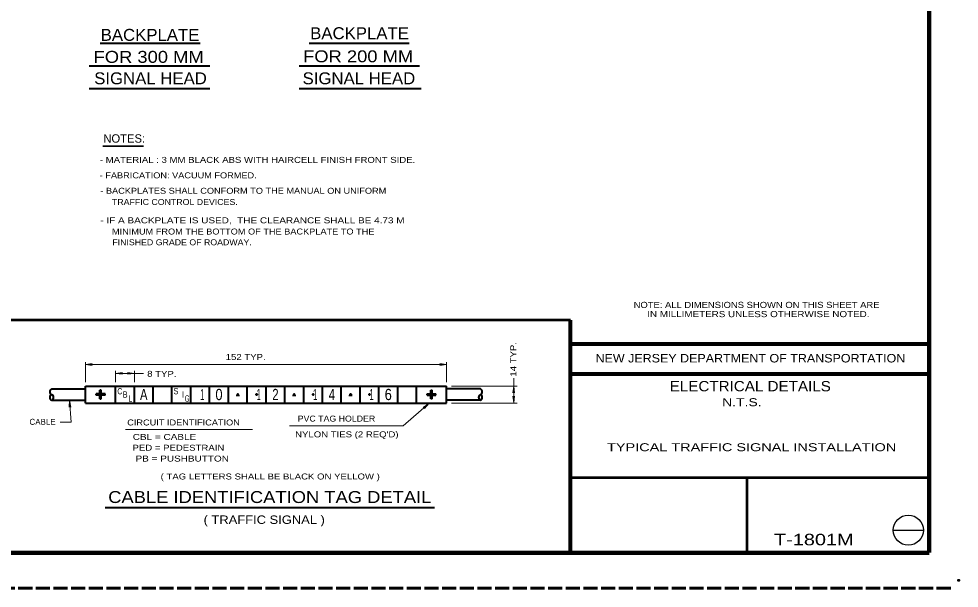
# Model space of a CAD drawing. Extents: x 312583 to 312853, y 144419 to 144586.
# Drawn here: x 312733 to 312852.8, y 144418.6 to 144491.1 of the extents above; entities that cross this region are included whole.
import ezdxf
from ezdxf.enums import TextEntityAlignment as Align

# ---------------------------------------------------------------- set-up
doc = ezdxf.new("R2010")
doc.units = 0
doc.header["$LTSCALE"] = 0.3
doc.header["$PDMODE"] = 32
doc.header["$PDSIZE"] = 0.15
doc.linetypes.add('LONG_DASHED', pattern=[7.5, 6, -1.5])
for name, color, linetype, lineweight in [('1', 7, 'Continuous', 40), ('10', 7, 'Continuous', 25), ('2', 7, 'Continuous', 13), ('63', 7, 'LONG_DASHED', 60)]:
    doc.layers.add(name, color=color, linetype=linetype, lineweight=lineweight)
doc.layers.add('5', color=7, linetype='Continuous')

msp = doc.modelspace()

# ---------------------------------------------------------------- linework, layer by layer
at = {"layer": '1', "lineweight": 158}
for p, q in [((312849, 144423.1446), (312849, 144585.0846)), ((312616.5, 144423.0846), (312849, 144423.0846))]:
    msp.add_line(p, q, dxfattribs=at)
at = {"layer": '1', "lineweight": 106}
msp.add_line((312849, 144423.1446), (312849, 144584.0756), dxfattribs=at)
at = {"layer": '1', "lineweight": 53}
for p, q in [((312803.31, 144452.7259), (312668.2732, 144452.7259)), ((312849, 144432.6666), (312803.31, 144432.6666)), ((312825.7546, 144432.6666), (312825.7546, 144423.1446))]:
    msp.add_line(p, q, dxfattribs=at)
at = {"layer": '1', "lineweight": 80}
for p, q in [((312803.31, 144423.1446), (312803.31, 144452.7259)), ((312803.31, 144449.7246), (312849, 144449.7246)), ((312803.31, 144445.9146), (312849, 144445.9146))]:
    msp.add_line(p, q, dxfattribs=at)
at = {"layer": '1'}
for p, q in [((312741.5243, 144442.1851), (312741.5243, 144444.3471)), ((312741.5243, 144444.3471), (312787.5243, 144444.3471)), ((312745.3576, 144442.1851), (312745.3576, 144444.3471)), ((312747.7496, 144442.1851), (312747.7496, 144444.3471)), ((312750.1493, 144442.1851), (312750.1493, 144444.3471)), ((312752.5413, 144442.1851), (312752.5413, 144444.3471)), ((312754.9409, 144442.1851), (312754.9409, 144444.3471)), ((312757.3329, 144442.1851), (312757.3329, 144444.3471)), ((312759.7326, 144442.1851), (312759.7326, 144444.3471)), ((312762.1246, 144442.1851), (312762.1246, 144444.3471)), ((312764.5243, 144442.1851), (312764.5243, 144444.3471)), ((312766.9239, 144442.1851), (312766.9239, 144444.3471)), ((312769.3159, 144442.1851), (312769.3159, 144444.3471)), ((312771.7156, 144442.1851), (312771.7156, 144444.3471)), ((312774.1076, 144442.1851), (312774.1076, 144444.3471)), ((312776.5073, 144442.1851), (312776.5073, 144444.3471)), ((312778.8993, 144442.1851), (312778.8993, 144444.3471)), ((312781.2989, 144442.1851), (312781.2989, 144444.3471)), ((312783.6909, 144442.1851), (312783.6909, 144444.3471)), ((312787.5243, 144442.1851), (312787.5243, 144444.3471)), ((312737.2156, 144443.9791), (312741.5243, 144443.9791)), ((312791.8329, 144443.9791), (312787.5243, 144443.9791)), ((312737.2156, 144442.5454), (312741.5243, 144442.5454)), ((312741.5243, 144442.1851), (312787.5243, 144442.1851)), ((312791.8329, 144442.5454), (312787.5243, 144442.5454)), ((312744.0476, 144428.8756), (312786.0013, 144428.8756))]:
    msp.add_line(p, q, dxfattribs=at)
at = {"layer": '1', "lineweight": 13}
msp.add_line((312739.6919, 144439.7317), (312738.2966, 144439.7317), dxfattribs=at)
at = {"layer": '1'}
for centre, start, end in [((312737.3699, 144443.6264), 113.18435, 246.81565), ((312737.3699, 144442.9057), 113.18435, 246.81565), ((312737.0613, 144442.9057), 293.18435, 66.81565), ((312791.9873, 144442.9057), 113.18435, 246.81565), ((312791.6786, 144443.6264), 293.18435, 66.81565), ((312791.6786, 144442.9057), 293.18435, 66.81565)]:
    msp.add_arc(centre, 0.392, start, end, dxfattribs=at)
for p in [(312743.4409, 144443.2661), (312760.9363, 144443.2661), (312763.3283, 144443.2661), (312768.1123, 144443.2661), (312770.5196, 144443.2661), (312775.2959, 144443.2661), (312777.7033, 144443.2661), (312785.6076, 144443.2661), (312852.75, 144419.5846)]:
    msp.add_point(p, dxfattribs=at)
at = {"layer": '10'}
msp.add_line((312844.4384, 144425.9659), (312848.2794, 144425.9659), dxfattribs=at)
msp.add_circle((312846.3494, 144425.9805), 1.9159, dxfattribs=at)
at = {"layer": '2', "lineweight": 40}
for p, q in [((312743.3954, 144488.0353), (312756.145, 144488.0353)), ((312770.0329, 144488.0353), (312782.7635, 144488.0353)), ((312741.9696, 144485.1603), (312757.3478, 144485.1603)), ((312768.7573, 144485.1603), (312784.0647, 144485.1603)), ((312741.9696, 144482.2853), (312757.3478, 144482.2853)), ((312768.7573, 144482.2853), (312784.2815, 144482.2853)), ((312742.8813, 144443.1741), (312742.8813, 144443.3504)), ((312743.3566, 144443.3504), (312742.8813, 144443.3504)), ((312743.3566, 144443.1741), (312742.8813, 144443.1741)), ((312743.5329, 144443.8334), (312743.3566, 144443.8334)), ((312743.3566, 144443.3504), (312743.3566, 144443.8334)), ((312743.3566, 144442.6987), (312743.3566, 144443.1741)), ((312743.5329, 144443.3504), (312743.5329, 144443.8334)), ((312744.0083, 144443.3504), (312743.5329, 144443.3504)), ((312743.5329, 144442.6987), (312743.5329, 144443.1741)), ((312744.0083, 144443.1741), (312743.5329, 144443.1741)), ((312744.0083, 144443.1741), (312744.0083, 144443.3504)), ((312785.0403, 144443.1741), (312785.0403, 144443.3504)), ((312785.0403, 144443.3504), (312785.5156, 144443.3504)), ((312785.0403, 144443.1741), (312785.5156, 144443.1741)), ((312785.5156, 144443.8334), (312785.6919, 144443.8334)), ((312785.5156, 144443.3504), (312785.5156, 144443.8334)), ((312785.5156, 144442.6987), (312785.5156, 144443.1741)), ((312785.6919, 144443.3504), (312785.6919, 144443.8334)), ((312785.6919, 144443.3504), (312786.1673, 144443.3504)), ((312785.6919, 144442.6987), (312785.6919, 144443.1741)), ((312785.6919, 144443.1741), (312786.1673, 144443.1741)), ((312786.1673, 144443.1741), (312786.1673, 144443.3504)), ((312743.3566, 144442.6987), (312743.5329, 144442.6987)), ((312785.6919, 144442.6987), (312785.5156, 144442.6987))]:
    msp.add_line(p, q, dxfattribs=at)
at = {"layer": '2', "lineweight": 35}
msp.add_line((312743.7271, 144474.9214), (312748.9321, 144474.9214), dxfattribs=at)
at = {"layer": '2'}
for p, q in [((312741.5243, 144444.8454), (312741.5243, 144447.3984)), ((312741.5243, 144447.0917), (312742.3906, 144447.1991)), ((312741.5243, 144447.0917), (312742.3906, 144446.9844)), ((312742.3906, 144447.1991), (312742.1146, 144447.0917)), ((312742.3906, 144446.9844), (312742.1146, 144447.0917)), ((312786.6579, 144447.1991), (312786.9339, 144447.0917)), ((312787.5243, 144447.0917), (312786.6579, 144447.1991)), ((312786.6579, 144446.9844), (312786.9339, 144447.0917)), ((312787.5243, 144447.0917), (312786.6579, 144446.9844)), ((312787.5243, 144444.8454), (312787.5243, 144447.3984)), ((312745.3576, 144444.8454), (312745.3576, 144446.2791)), ((312745.3576, 144445.9571), (312746.2239, 144446.0644)), ((312747.7496, 144445.9571), (312745.3576, 144445.9571)), ((312745.3576, 144445.9571), (312746.2239, 144445.8497)), ((312746.2239, 144446.0644), (312745.9479, 144445.9571)), ((312746.2239, 144445.8497), (312745.9479, 144445.9571)), ((312746.8833, 144446.0644), (312747.1593, 144445.9571)), ((312747.7496, 144445.9571), (312746.8833, 144446.0644)), ((312746.8833, 144445.8497), (312747.1593, 144445.9571)), ((312747.7496, 144445.9571), (312746.8833, 144445.8497)), ((312747.7496, 144444.8454), (312747.7496, 144446.2791)), ((312748.8919, 144445.9571), (312747.7496, 144445.9571)), ((312796.5019, 144444.3471), (312788.1376, 144444.3471)), ((312796.0879, 144444.3471), (312795.9806, 144443.4807)), ((312796.0879, 144442.1927), (312796.0879, 144445.3555)), ((312796.0879, 144444.3471), (312796.1953, 144443.4807)), ((312795.9806, 144443.4807), (312796.0879, 144443.7567)), ((312795.9806, 144443.0591), (312796.0879, 144442.7831)), ((312796.0879, 144442.1927), (312795.9806, 144443.0591)), ((312796.1953, 144443.4807), (312796.0879, 144443.7567)), ((312796.1953, 144443.0591), (312796.0879, 144442.7831)), ((312796.0879, 144442.1927), (312796.1953, 144443.0591)), ((312739.4849, 144442.5301), (312739.4543, 144441.6637)), ((312739.4543, 144441.6637), (312739.5463, 144441.9474)), ((312739.6919, 144439.7317), (312739.4849, 144442.5301)), ((312739.4849, 144442.5301), (312739.6536, 144441.6714)), ((312739.6536, 144441.6714), (312739.5463, 144441.9474)), ((312785.2779, 144442.1161), (312782.0043, 144439.2717)), ((312785.2779, 144442.1161), (312784.5573, 144441.6254)), ((312785.2779, 144442.1161), (312784.6953, 144441.4644)), ((312796.5019, 144442.1851), (312788.1376, 144442.1851)), ((312784.5573, 144441.6254), (312784.8333, 144441.7251)), ((312784.6953, 144441.4644), (312784.8333, 144441.7251)), ((312746.6149, 144438.7887), (312762.7993, 144438.7887)), ((312782.0043, 144439.2717), (312767.4915, 144439.2717))]:
    msp.add_line(p, q, dxfattribs=at)
at = {"layer": '2', "lineweight": 25}
for p, q in [((312741.5243, 144444.3471), (312741.5473, 144444.3471)), ((312787.5243, 144444.3471), (312787.5013, 144444.3471))]:
    msp.add_line(p, q, dxfattribs=at)
at = {"layer": '2'}
msp.add_lwpolyline([(312787.5243, 144447.0917), (312758.4009, 144447.0917), (312741.5243, 144447.0917)], dxfattribs=at)
for p in [(312743.4409, 144443.2661), (312785.6076, 144443.2661)]:
    msp.add_point(p, dxfattribs=at)
at = {"layer": '63'}
msp.add_line((312851.75, 144418.5846), (312583.526, 144418.5846), dxfattribs=at)

# ---------------------------------------------------------------- texts
at = {"layer": '1'}
for s, width, p in [('NOTE: ALL DIMENSIONS SHOWN ON THIS SHEET ARE', 1.15, (312811.3493, 144454.2975)), ('     IN MILLIMETERS UNLESS OTHERWISE NOTED.', 1.2, (312811.3492, 144453.1275))]:
    msp.add_text(s, height=0.78, dxfattribs=dict(at, width=width)).set_placement(p)
for s, height, width, p in [('NEW JERSEY DEPARTMENT OF TRANSPORTATION', 1.08, 1.1, (312826.2285, 144447.3546)), ('ELECTRICAL DETAILS', 1.315, 1.1, (312826.2107, 144443.6759)), ('C', 0.8064, 0.65, (312745.8981, 144443.2891)), ('B', 0.805, 0.7, (312746.5727, 144442.8674)), ('L', 0.805, 0.75, (312747.232, 144442.3537)), ('A', 1.434, 0.75, (312748.9456, 144442.5531)), ('S', 0.8064, 0.7, (312753.0472, 144443.2967)), ('I', 0.805, 0.85, (312753.9481, 144442.8597)), ('G', 0.805, 0.6, (312754.4694, 144442.3537)), ('1', 1.434, 0.5, (312756.4014, 144442.5531)), ('0', 1.434, 0.85, (312758.529, 144442.5531)), ('1', 1.434, 0.5, (312763.5928, 144442.5531)), ('2', 1.434, 0.75, (312765.7202, 144442.5531)), ('1', 1.434, 0.5, (312770.7841, 144442.5531)), ('4', 1.434, 0.75, (312772.9116, 144442.5531)), ('1', 1.434, 0.5, (312777.9678, 144442.5531)), ('6', 1.434, 0.85, (312780.0953, 144442.5531))]:
    msp.add_text(s, height=height, dxfattribs=dict(at, width=width)).set_placement(p, align=Align.CENTER)
for p in [(312760.9401, 144442.5531), (312768.1161, 144442.5531), (312775.2997, 144442.5531)]:
    msp.add_text('-', height=1.434, dxfattribs=at).set_placement(p, align=Align.CENTER)
at = {"layer": '2'}
for s, height, width, p in [('BACKPLATE', 1.52, 1.05, (312749.7446, 144488.3402)), ('BACKPLATE', 1.52, 1.05, (312776.434, 144488.553)), ('FOR 300 MM', 1.52, 1.15, (312749.5658, 144485.536)), ('FOR 200 MM', 1.52, 1.15, (312776.2553, 144485.6069)), ('SIGNAL HEAD', 1.52, 1.05, (312749.8059, 144482.803)), ('SIGNAL HEAD', 1.52, 1.05, (312776.3537, 144482.8029)), ('    N.T.S.  ', 1.02, 1.3, (312824.6461, 144441.778)), ('     TYPICAL TRAFFIC SIGNAL INSTALLATION     ', 1.02, 1.35, (312826.3871, 144436.0399)), ('CABLE IDENTIFICATION TAG DETAIL', 1.52, 1.15, (312765.0009, 144429.4413)), ('( TRAFFIC SIGNAL )', 1.07, 1.15, (312764.29, 144426.7803))]:
    msp.add_text(s, height=height, dxfattribs=dict(at, width=width)).set_placement(p, align=Align.CENTER)
msp.add_text('NOTES:', height=1.07, dxfattribs=at).set_placement((312746.4568, 144475.3629), align=Align.CENTER)
for s, width, p in [('- MATERIAL : 3 MM BLACK ABS WITH HAIRCELL FINISH FRONT SIDE.', 1.2, (312743.3518, 144472.791)), ('- FABRICATION: VACUUM FORMED.', 1.15, (312743.3349, 144470.8168)), ('- BACKPLATES SHALL CONFORM TO THE MANUAL ON UNIFORM', 1.15, (312743.4147, 144468.8504)), ('TRAFFIC CONTROL DEVICES.', 1.1, (312744.8943, 144467.4244)), ('- IF A BACKPLATE IS USED,  THE CLEARANCE SHALL BE 4.73 M', 1.25, (312743.4147, 144465.086)), ('MINIMUM FROM THE BOTTOM OF THE BACKPLATE TO THE', 1.15, (312744.8943, 144463.66)), ('FINISHED GRADE OF ROADWAY.', 1.1, (312744.9403, 144462.2877)), ('152 TYP.', 1.2, (312759.3846, 144447.6697)), ('8 TYP.', 1.2, (312749.3844, 144445.521)), ('PVC TAG HOLDER', 1.1, (312768.5572, 144439.8208)), ('CIRCUIT IDENTIFICATION', 1.15, (312746.8373, 144439.3244)), ('  CBL = CABLE', 1.25, (312746.8373, 144437.4844)), ("NYLON TIES (2 REQ'D)", 1.2, (312768.2272, 144437.8103)), ('  PED = PEDESTRAIN', 1.2, (312746.8373, 144436.1044)), ('   PB = PUSHBUTTON', 1.25, (312746.8373, 144434.7244)), ('( TAG LETTERS SHALL BE BLACK ON YELLOW )', 1.2, (312751.0978, 144432.4398))]:
    msp.add_text(s, height=0.76, dxfattribs=dict(at, width=width)).set_placement(p)
at = {"layer": '2', "width": 1.2}
msp.add_text('14 TYP.', height=0.76, rotation=90, dxfattribs=at).set_placement((312796.4025, 144445.5523))
at = {"layer": '2'}
msp.add_text('CABLE', height=0.76, dxfattribs=at).set_placement((312734.3881, 144439.4068))
at = {"layer": '5', "width": 1.3}
msp.add_text('T-1801M   ', height=1.457, dxfattribs=at).set_placement((312835.3614, 144424.0569), align=Align.CENTER)

doc.saveas('drawing.dxf')
